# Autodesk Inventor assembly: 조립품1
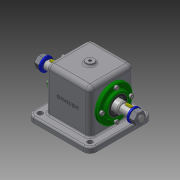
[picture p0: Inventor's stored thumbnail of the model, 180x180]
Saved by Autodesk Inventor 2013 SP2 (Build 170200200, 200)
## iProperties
Created: 2022-07
Part Number: 조립품1
Document SubType Name: Assembly
Designer: a
Author: a
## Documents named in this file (12)
- C:\Users\a\Desktop\720706V1011\조립품1.iam
- C:\Users\a\Desktop\720706V1011\본체.ipt
- C:\Users\a\Desktop\720706V1011\V벨트풀리.ipt
- C:\Users\a\Desktop\720706V1011\너트 M12x1.25.ipt
- C:\Users\a\Desktop\720706V1011\베어링 6204.ipt
- C:\Users\a\Desktop\720706V1011\볼트 M4x0.7.ipt
- C:\Users\a\Desktop\720706V1011\스퍼기어.ipt
- C:\Users\a\Desktop\720706V1011\오일실 20x35x8.ipt
- C:\Users\a\Desktop\720706V1011\와셔 12x24.ipt
- C:\Users\a\Desktop\720706V1011\축.ipt
- C:\Users\a\Desktop\720706V1011\커버.ipt
- C:\Users\a\Desktop\720706V1011\키 5x5.ipt
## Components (1 placed, 1 different names)
1. V벨트풀리:1
